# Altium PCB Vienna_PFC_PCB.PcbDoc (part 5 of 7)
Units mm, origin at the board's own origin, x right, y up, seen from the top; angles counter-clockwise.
Board outline 447.04 x 302.51 mm, 6 copper layers (Top Layer, Signal Layer 1, Signal Layer 2, Signal Layer 3, Signal Layer 4, Bottom Layer), stack 1.231 mm thick; 630 components, 255 nets, 1656 pads, 941 vias.
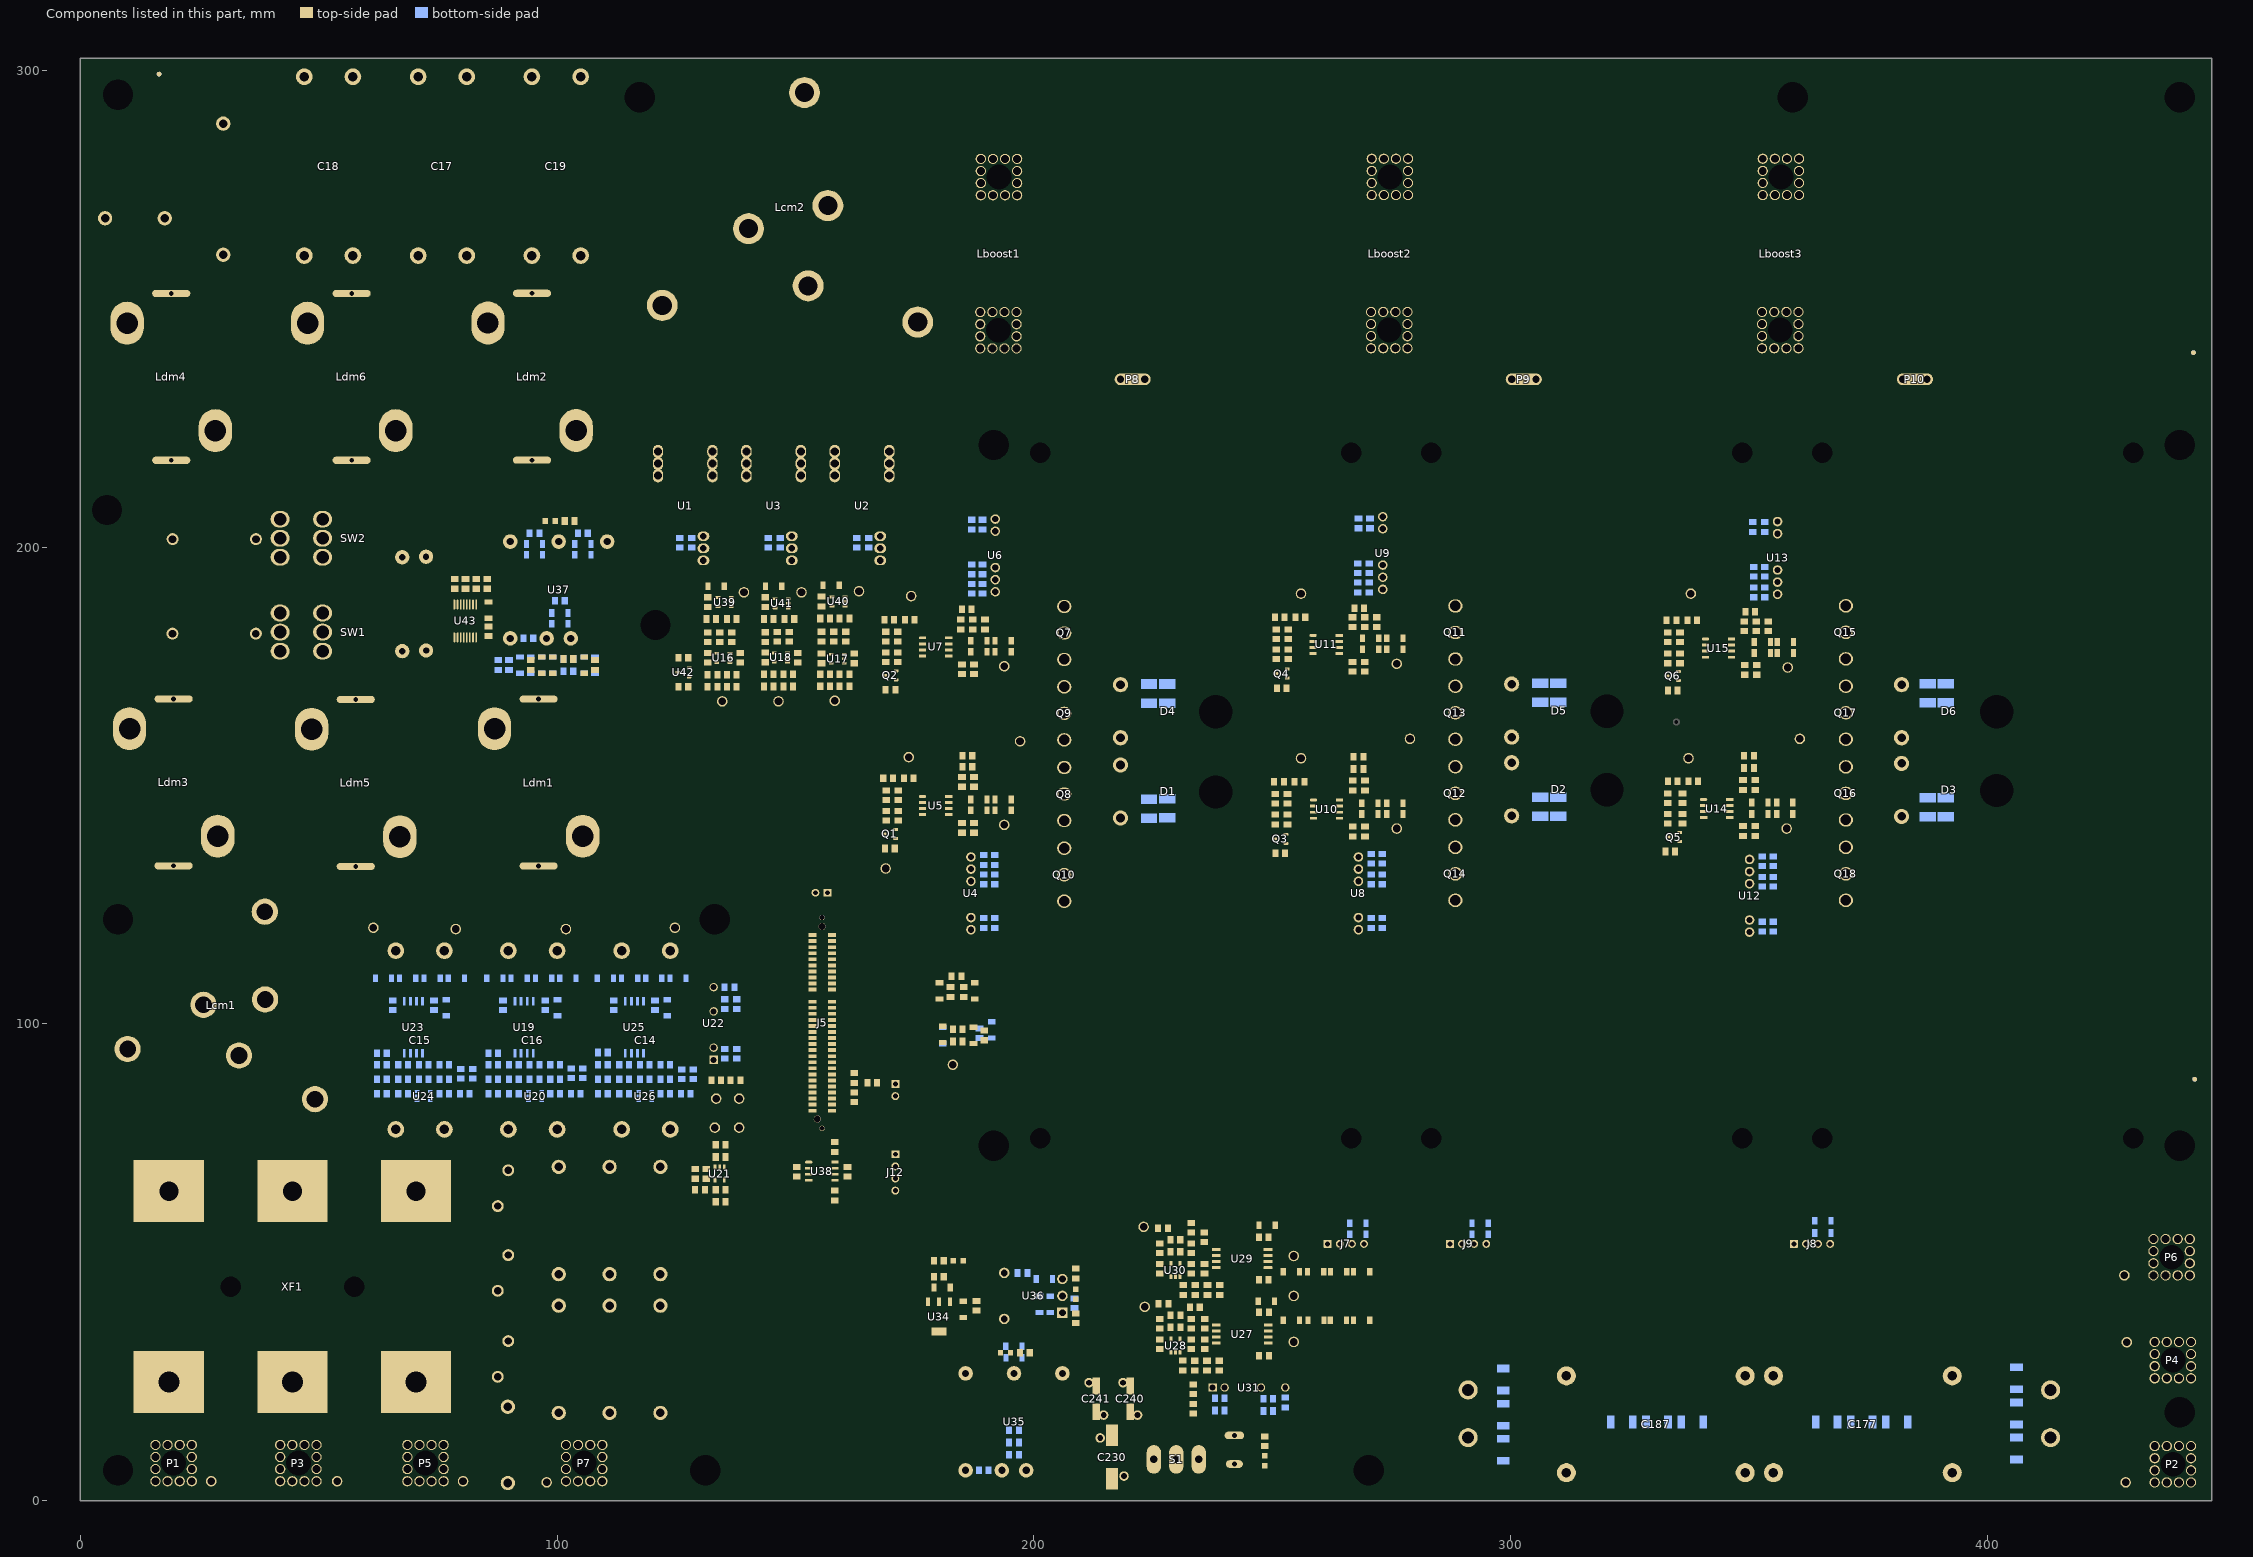
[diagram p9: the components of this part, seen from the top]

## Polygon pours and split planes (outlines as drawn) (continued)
NetQ17_1 on Top Layer "NONET_L-01_P-001" (solid, remove dead copper, pour order 825): 358.902,178.562 358.902,168.656 371.602,168.656 371.602,170.942 363.982,178.562
NetQ14_1 on Top Layer "NONET_L-01_P-001" (solid, remove dead copper, pour order 823): 276.86,144.78 276.86,134.874 289.56,134.874 289.56,137.16 281.94,144.78
NetQ13_1 on Top Layer "NONET_L-01_P-001" (solid, remove dead copper, pour order 821): 276.86,179.324 276.86,169.418 289.56,169.418 289.56,171.704 281.94,179.324
NetQ10_1 on Top Layer "NONET_L-01_P-001" (solid, remove dead copper, pour order 819): 194.818,145.542 194.818,135.636 207.01,135.89 207.01,137.922 199.898,145.542
NetQ16_1 on Top Layer "NONET_L-01_P-001" (solid, remove dead copper, pour order 817): 358.648,145.796 363.728,145.796 371.094,153.162 371.348,153.416 371.348,155.448 365.252,155.448 358.902,155.448 358.648,155.448
NetQ11_1 on Top Layer "NONET_L-01_P-001" (solid, remove dead copper, pour order 815): 276.86,180.086 281.94,180.086 289.306,187.452 289.56,187.706 289.56,189.738 283.464,189.738 277.114,189.738 276.86,189.738
NetQ15_1 on Top Layer "NONET_L-01_P-001" (solid, remove dead copper, pour order 813): 358.902,179.324 363.982,179.324 371.348,186.69 371.602,186.944 371.602,188.976 365.506,188.976 359.156,188.976 358.902,188.976
NetQ12_1 on Top Layer "NONET_L-01_P-001" (solid, remove dead copper, pour order 811): 276.86,145.542 281.94,145.542 289.306,152.908 289.56,153.162 289.56,155.194 283.464,155.194 277.114,155.194 276.86,155.194
NetQ8_1 on Top Layer "NONET_L-01_P-001" (solid, remove dead copper, pour order 807): 194.818,146.304 200.66,146.304 207.518,153.162 207.518,155.956 201.422,155.956 195.072,155.956 194.818,155.956
NetQ7_1 on Top Layer "NONET_L-01_P-001" (solid, remove dead copper, pour order 805): 194.818,179.578 199.898,179.578 207.264,186.944 207.518,187.198 207.518,189.23 201.422,189.23 195.072,189.23 194.818,189.23
NetQ9_1 on Top Layer "NONET_L-01_P-001" (solid, remove dead copper, pour order 803): 194.818,178.816 194.818,168.91 206.248,168.91 207.518,171.196 199.898,178.816
NetLcm1_1 on Top Layer "NONET_L-01_P-001" (solid, remove dead copper, pour order 42): 25 vertices, not listed, extent 2.542,32.512 90.932,108.966
NetLcm1_5 on Top Layer "NONET_L-01_P-001" (solid, remove dead copper, pour order 30): 91.186,54.864 91.186,50.038 85.344,44.196 59.436,44.196 49.784,44.196 35.814,58.166 28.194,65.786 28.194,81.026 28.194,97.536 36.322,97.536 36.322,77.724 42.418,71.628 52.578,71.628 52.578,61.468 59.182,54.864
NetLcm1_3 on Top Layer "NONET_L-01_P-001" (solid, remove dead copper, pour order 18): 24 vertices, not listed, extent 34.29,56.896 91.694,109.22
VBUSP on Top Layer "NONET_L-01_P-001" (solid, pour order 480): 424.205,99.06 420.37,99.06 205.232,99.06 205.232,66.294 424.205,66.294
NetD1_2 on Top Layer "NONET_L-01_P-001" (solid, remove dead copper, pour order 618): 26 vertices, not listed, extent 186.69,153.162 262.89,251.206
NetD2_2 on Top Layer "NONET_L-01_P-001" (solid, remove dead copper, pour order 630): 26 vertices, not listed, extent 268.986,153.67 344.424,251.206
V_BUS_M on Top Layer "NONET_L-01_P-001" (solid, remove dead copper, pour order 724): 18 vertices, not listed, extent 368.3,98.044 444.5,299.72
V_BUS_M on Top Layer "NONET_L-01_P-001" (solid, remove dead copper, pour order 728): 425.958,102.616 425.958,99.06 420.878,99.06 420.878,84.582 420.878,83.82 424.688,83.82 444.5,83.82 444.5,102.616
PE on Top Layer "NONET_L-01_P-001" (solid, remove dead copper, pour order 787): 123.698,2.286 123.698,64.77 98.552,64.77 98.552,2.286
DGND on Top Layer "NONET_L-01_P-001" (solid, pour order 860): 202.438,90.17 202.438,124.206 184.404,124.206 184.404,90.17
NetD3_2 on Top Layer "NONET_L-01_P-001" (solid, remove dead copper, pour order 642): 24 vertices, not listed, extent 351.028,153.67 422.91,251.206
VBUSP on Top Layer "NONET_L-01_P-001" (solid, remove dead copper, pour order 978): 393.7,102.87 381.254,102.87 381.254,142.748 382.778,144.272 393.7,144.272
VBUSN on Top Layer "NONET_L-01_P-001" (solid, remove dead copper, pour order 988): 396.722,102.888 421.36,102.888 421.36,175.292 408.674,175.292 380.652,175.292 380.652,171.535 380.72,171.468 385.546,171.468 393.928,171.468 395.198,170.198 396.722,168.674
GND on Signal Layer 1 "NONET_L-01_P-001" (solid, remove dead copper, pour order 1492): 55 vertices, not listed, extent 88.392,2.54 240.538,203.708
+3.3V_D on Signal Layer 1 "NONET_L-01_P-001" (solid, remove dead copper, pour order 496): 198.12,208.534 181.356,208.534 165.371,192.549 165.354,132.08 181.864,115.57 202.438,115.57 202.438,124.206 185.42,124.206 181.864,124.206 177.8,128.27 176.53,129.54 176.53,189.23 176.53,198.374 180.34,202.184 198.12,202.184
V_BUS_M on Signal Layer 1 "NONET_L-01_P-001" (solid, remove dead copper, pour order 1068): 34 vertices, not listed, extent 368.554,90.678 393.192,168.91
V_BUS_M on Signal Layer 1 "NONET_L-01_P-001" (solid, remove dead copper, pour order 708): 17 vertices, not listed, extent 205.232,2.032 444.5,99.06
GND on Signal Layer 1 "NONET_L-01_P-001" (solid, remove dead copper, pour order 837): 61.468,96.52 61.366,96.418 61.366,84.328 61.366,84.176 62.992,82.55 84.328,82.55 139.954,82.55 139.954,96.52
+3.3V_D on Signal Layer 1 "NONET_L-01_P-001" (solid, remove dead copper, pour order 532): 361.95,207.772 330.2,207.772 330.2,184.404 330.2,132.842 330.2,102.87 361.95,102.87 361.95,123.444 349.25,123.444 345.694,123.444 341.63,127.508 340.36,128.778 340.36,188.468 340.36,197.612 344.17,201.422 361.95,201.422
PE on Signal Layer 1 "NONET_L-01_P-001" (solid, remove dead copper, pour order 795): 123.698,2.159 123.698,64.77 98.298,64.77 98.298,2.159 110.871,2.159
NetC10_2 on Signal Layer 1 "NONET_L-01_P-001" (solid, remove dead copper, pour order 1252): 26 vertices, not listed, extent 36.068,120.904 110.236,145.796
DGND2 on Signal Layer 1 "NONET_L-01_P-001" (solid, remove dead copper, pour order 1490): 89.281,171.45 82.423,171.45 82.042,171.45 78.232,175.26 77.47,176.022 77.47,191.008 78.232,191.77 85.852,191.77 85.979,191.77 86.233,191.516 86.614,191.135 86.614,185.674 86.614,177.292 89.281,174.625
NetC20_1 on Signal Layer 1 "NONET_L-01_P-001" (solid, remove dead copper, pour order 1442): 12.7,276.86 10.16,274.32 10.16,264.16 12.7,261.62 13.97,260.35 30.48,260.35 33.02,262.89 33.782,263.652 33.782,273.812 30.734,276.86
NetC17_1 on Signal Layer 1 "NONET_L-01_P-001" (solid, remove dead copper, pour order 1430): 110.744,297.18 107.95,299.974 107.696,300.228 104.902,300.228 20.828,300.228 15.748,295.402 10.922,290.322 10.16,289.56 4.572,289.56 2.54,287.528 2.54,282.956 4.572,280.924 40.132,280.924 107.442,280.924 110.513,283.995
NetLboost3_1 on Signal Layer 1 "NONET_L-01_P-001" (solid, remove dead copper, pour order 1418): 38 vertices, not listed, extent 137.16,263.398 362.458,300.228
NetLboost2_1 on Signal Layer 1 "NONET_L-01_P-001" (solid, remove dead copper, pour order 1406): 20 vertices, not listed, extent 148.844,265.176 280.416,293.37
NetLboost1_1 on Signal Layer 1 "NONET_L-01_P-001" (solid, remove dead copper, pour order 1394): 150.114,256.286 151.384,255.016 151.384,252.476 172.466,252.476 189.23,269.24 195.58,269.24 198.374,272.034 198.374,282.448 197.612,283.21 178.054,283.21 152.4,257.556
NetLcm2_3 on Signal Layer 1 "NONET_L-01_P-001" (solid, remove dead copper, pour order 1382): 161.29,247.65 161.29,231.14 163.83,228.6 163.83,214.122 167.64,210.312 173.99,210.312 177.492,210.312 180.34,212.658 180.34,236.982 180.34,248.92 177.8,251.46 164.754,251.46
NetLcm2_5 on Signal Layer 1 "NONET_L-01_P-001" (solid, remove dead copper, pour order 1370): 32 vertices, not listed, extent 118.618,213.36 159.004,299.72
NetLcm2_1 on Signal Layer 1 "NONET_L-01_P-001" (solid, remove dead copper, pour order 1358): 123.444,254.254 117.856,248.666 120.65,245.872 128.27,238.252 128.27,228.092 128.27,215.392 129.794,213.868 130.302,213.36 133.35,213.36 134.112,213.36 135.128,214.376 135.636,214.884 135.636,235.966 135.636,242.062 131.318,246.38
NetC19_2 on Signal Layer 1 "NONET_L-01_P-001" (solid, remove dead copper, pour order 1348): 25 vertices, not listed, extent 77.47,212.852 125.222,264.16
NetC17_2 on Signal Layer 1 "NONET_L-01_P-001" (solid, remove dead copper, pour order 1334): 34 vertices, not listed, extent 44.196,213.614 143.51,278.13
NetC18_2 on Signal Layer 1 "NONET_L-01_P-001" (solid, remove dead copper, pour order 1322): 51 vertices, not listed, extent 5.08,205.232 162.814,278.13
NetLdm2_1 on Signal Layer 1 "NONET_L-01_P-001" (solid, remove dead copper, pour order 1308): 27 vertices, not listed, extent 46.99,175.26 107.442,231.648
NetLdm6_1 on Signal Layer 1 "NONET_L-01_P-001" (solid, remove dead copper, pour order 1298): 47.752,196.596 48.26,196.088 53.848,196.088 54.356,196.596 54.61,196.85 54.61,207.518 63.5,216.408 70.866,223.774 70.866,228.346 68.58,230.632 53.594,230.632 43.434,230.632 40.894,228.092 40.894,212.852 47.752,205.994
NetC16_2 on Signal Layer 1 "NONET_L-01_P-001" (solid, remove dead copper, pour order 1288): 27 vertices, not listed, extent 34.544,156.21 99.06,189.23
NetC15_2 on Signal Layer 1 "NONET_L-01_P-001" (solid, remove dead copper, pour order 1276): 31 vertices, not listed, extent 2.54,154.432 38.862,230.124
NetC15_2 on Signal Layer 1 "NONET_L-01_P-001" (solid, remove dead copper, pour order 1278): 31 vertices, not listed, extent 2.54,154.432 38.862,230.124
NetC14_2 on Signal Layer 1 "NONET_L-01_P-001" (solid, remove dead copper, pour order 1266): 30 vertices, not listed, extent 10.414,154.686 52.07,209.296
NetC8_2 on Signal Layer 1 "NONET_L-01_P-001" (solid, remove dead copper, pour order 1232): 32 vertices, not listed, extent 26.292,81.156 70.104,146.434
NetC9_2 on Signal Layer 1 "NONET_L-01_P-001" (solid, remove dead copper, pour order 1222): 17 vertices, not listed, extent 2.54,90.17 32.258,146.812
NetD3_2 on Signal Layer 1 "NONET_L-01_P-001" (solid, pour order 1170): 362.287,237.744 366.859,233.172 362.287,233.172
NetD2_2 on Signal Layer 1 "NONET_L-01_P-001" (solid, pour order 1156): 280.162,237.578 284.734,233.006 280.162,233.006
NetD1_2 on Signal Layer 1 "NONET_L-01_P-001" (solid, pour order 1144): 197.949,237.744 202.521,233.172 197.949,233.172
NetD3_2 on Signal Layer 1 "NONET_L-01_P-001" (solid, pour order 1130): 366.903,207.137 361.061,212.979 366.903,212.979
NetD2_2 on Signal Layer 1 "NONET_L-01_P-001" (solid, pour order 1122): 331.089,212.725 325.247,206.883 325.247,212.725
NetD2_2 on Signal Layer 1 "NONET_L-01_P-001" (solid, pour order 1112): 286.004,207.645 280.162,213.487 286.004,213.487
NetD1_2 on Signal Layer 1 "NONET_L-01_P-001" (solid, pour order 1102): 249.682,214.63 243.84,208.788 243.84,214.63
NetD1_2 on Signal Layer 1 "NONET_L-01_P-001" (solid, pour order 1094): 203.498,207.518 197.656,213.36 203.498,213.36
NetTVS1_1 on Signal Layer 1 "NONET_L-01_P-001" (solid, remove dead copper, pour order 1074): 24 vertices, not listed, extent 86.233,18.034 96.139,63.246
V_N_MEAS on Signal Layer 1 "NONET_L-01_P-001" (solid, remove dead copper, pour order 847): 135.636,101.6 61.468,101.6 61.214,101.854 61.214,110.49 135.636,110.49
+3.3V_D on Signal Layer 1 "NONET_L-01_P-001" (solid, remove dead copper, pour order 536): 361.696,105.664 184.15,105.664 184.15,117.348 301.752,117.348 361.586,117.348 361.696,117.238
+3.3V_D on Signal Layer 1 "NONET_L-01_P-001" (solid, remove dead copper, pour order 526): 280.162,208.788 248.412,208.788 248.412,185.42 248.412,133.858 248.412,102.87 280.162,102.87 280.162,124.46 267.462,124.46 263.906,124.46 259.842,128.524 258.572,129.794 258.572,189.484 258.572,198.628 262.382,202.438 280.162,202.438
NetLcm1_3 on Signal Layer 1 "NONET_L-01_P-001" (solid, remove dead copper, pour order 58): 24 vertices, not listed, extent 34.29,56.896 91.694,109.22
NetLcm1_1 on Signal Layer 1 "NONET_L-01_P-001" (solid, remove dead copper, pour order 46): 25 vertices, not listed, extent 2.545,31.496 91.186,108.966
NetLcm1_5 on Signal Layer 1 "NONET_L-01_P-001" (solid, remove dead copper, pour order 34): 90.932,54.865 90.932,49.7 85.429,44.197 59.521,44.197 49.869,44.197 35.899,58.167 28.279,65.787 28.279,81.027 28.279,97.537 36.407,97.537 36.407,77.725 42.503,71.629 52.663,71.629 52.663,61.469 59.267,54.865
+20V1 on Signal Layer 1 "NONET_L-01_P-001" (solid, remove dead copper, pour order 570): 182.88,198.12 182.88,162.56 198.12,162.56 198.12,198.12
-5V2 on Signal Layer 1 "NONET_L-01_P-001" (solid, remove dead copper, pour order 572): 182.88,127.762 198.12,127.762 198.12,157.48 182.88,157.48
+20V3 on Signal Layer 1 "NONET_L-01_P-001" (solid, remove dead copper, pour order 574): 264.922,198.628 264.922,162.56 280.162,162.56 280.162,198.628
-5V4 on Signal Layer 1 "NONET_L-01_P-001" (solid, remove dead copper, pour order 576): 264.922,127.508 280.162,127.508 280.162,157.48 264.922,157.48
+20V5 on Signal Layer 1 "NONET_L-01_P-001" (solid, remove dead copper, pour order 578): 346.71,197.866 346.71,162.56 361.95,162.56 361.95,197.866
-5V6 on Signal Layer 1 "NONET_L-01_P-001" (solid, remove dead copper, pour order 580): 346.71,126.746 361.95,126.746 361.95,157.48 346.71,157.48
NetD1_2 on Signal Layer 1 "NONET_L-01_P-001" (solid, remove dead copper, pour order 628): 26 vertices, not listed, extent 186.69,153.162 262.89,251.206
NetD2_2 on Signal Layer 1 "NONET_L-01_P-001" (solid, remove dead copper, pour order 640): 26 vertices, not listed, extent 268.986,153.67 344.424,251.206
NetD3_2 on Signal Layer 1 "NONET_L-01_P-001" (solid, remove dead copper, pour order 652): 24 vertices, not listed, extent 351.028,153.67 422.91,251.206
V_BUS_M on Signal Layer 1 "NONET_L-01_P-001" (solid, remove dead copper, pour order 720): 18 vertices, not listed, extent 368.3,98.044 444.5,299.72
V_BUS_M on Signal Layer 1 "NONET_L-01_P-001" (solid, remove dead copper, pour order 767): 246.38,17.526 246.38,58.674 255.778,58.674 255.778,47.752 255.778,17.78
VBUSP on Signal Layer 1 "NONET_L-01_P-001" (solid, remove dead copper, pour order 906): 230.124,120.65 217.678,120.65 217.678,142.748 219.202,144.272 230.124,144.272
VBUSN on Signal Layer 1 "NONET_L-01_P-001" (solid, remove dead copper, pour order 924): 232.918,120.65 245.11,120.65 245.11,175.514 244.87,175.274 216.849,175.274 216.849,171.517 216.916,171.45 221.742,171.45 230.124,171.45 231.394,170.18 232.918,168.656
VBUSP on Signal Layer 1 "NONET_L-01_P-001" (solid, remove dead copper, pour order 944): 312.166,120.65 299.72,120.65 299.72,142.748 301.244,144.272 312.166,144.272
VBUSN on Signal Layer 1 "NONET_L-01_P-001" (solid, remove dead copper, pour order 954): 314.96,120.65 326.898,120.65 326.898,139.192 326.898,175.26 326.949,175.311 326.912,175.274 298.891,175.274 298.891,171.517 298.958,171.45 303.784,171.45 312.166,171.45 313.436,170.18 314.96,168.656
VBUSP on Signal Layer 1 "NONET_L-01_P-001" (solid, remove dead copper, pour order 976): 393.7,102.87 381.254,102.87 381.254,142.748 382.778,144.272 393.7,144.272
VBUSN on Signal Layer 1 "NONET_L-01_P-001" (solid, remove dead copper, pour order 986): 396.722,102.888 421.36,102.888 421.36,175.292 408.674,175.292 380.652,175.292 380.652,171.535 380.72,171.468 385.546,171.468 393.928,171.468 395.198,170.198 396.722,168.674
GND1 on Signal Layer 1 "NONET_L-01_P-001" (solid, remove dead copper, pour order 1018): 34 vertices, not listed, extent 198.628,124.206 208.534,189.23
V_BUS_M on Signal Layer 1 "NONET_L-01_P-001" (solid, remove dead copper, pour order 1028): 34 vertices, not listed, extent 204.978,120.65 229.616,168.402
GND3 on Signal Layer 1 "NONET_L-01_P-001" (solid, remove dead copper, pour order 1036): 25 vertices, not listed, extent 280.67,124.238 289.572,189.738
V_BUS_M on Signal Layer 1 "NONET_L-01_P-001" (solid, remove dead copper, pour order 1046): 34 vertices, not listed, extent 287.02,120.65 311.658,168.91
GND5 on Signal Layer 1 "NONET_L-01_P-001" (solid, remove dead copper, pour order 1056): 25 vertices, not listed, extent 362.458,124.238 371.36,188.976
GND3 on Signal Layer 1 "NONET_L06_P1054" (solid, remove dead copper, pour order 1054): 25 vertices, not listed, extent 362.458,124.238 371.36,188.976
GND_IN on Signal Layer 1 "NONET_L-01_P-001" (solid, remove dead copper, pour order 1470): 189.23,14.986 183.896,9.652 181.102,6.858 181.102,4.064 181.102,3.81 182.88,2.032 190.246,2.032 254,2.032 255.27,3.302 255.27,14.478 254.762,14.986
12V_IN on Signal Layer 1 "NONET_L-01_P-001" (solid, remove dead copper, pour order 1472): 261.62,62.23 260.35,60.96 260.35,52.578 261.62,51.308 295.91,51.308 296.164,51.308 297.18,52.324 297.18,58.928 297.18,60.706 295.656,62.23
+3.3V on Signal Layer 2 "NONET_L-01_P-001" (solid, remove dead copper, pour order 1188): 54 vertices, not listed, extent 88.392,2.54 240.538,200.914
V_BUS_M on Signal Layer 2 "NONET_L-01_P-001" (solid, remove dead copper, pour order 1026): 35 vertices, not listed, extent 204.978,102.87 229.616,168.402
VBUSN on Signal Layer 2 "NONET_L-01_P-001" (solid, remove dead copper, pour order 922): 232.918,102.87 245.11,102.87 245.11,175.514 244.87,175.274 216.849,175.274 216.849,171.517 216.916,171.45 221.742,171.45 230.124,171.45 231.394,170.18 232.918,168.656
DGND on Signal Layer 2 "NONET_L-01_P-001" (solid, remove dead copper, pour order 534): 361.95,102.87 201.93,102.87 201.93,90.17 184.15,90.17 184.15,117.348 302.006,117.348 361.84,117.348 361.95,117.238
DGND on Signal Layer 2 "NONET_L-01_P-001" (solid, remove dead copper, pour order 310): 19 vertices, not listed, extent 166.37,115.57 202.438,208.534
VBUSN on Signal Layer 2 "NONET_L-01_P-001" (solid, remove dead copper, pour order 1494): 396.722,93.472 421.36,93.472 421.36,175.292 408.674,175.292 380.652,175.292 380.652,171.535 380.72,171.468 385.546,171.468 393.928,171.468 395.198,170.198 396.722,168.674
DGND on Signal Layer 2 "NONET_L-01_P-001" (solid, remove dead copper, pour order 312): 280.162,208.788 248.412,208.788 248.412,185.42 248.412,133.858 248.412,102.87 280.162,102.87 280.162,124.46 267.462,124.46 263.906,124.46 259.842,128.524 258.572,129.794 258.572,189.484 258.572,198.628 262.382,202.438 280.162,202.438
V_BUS_M on Signal Layer 2 "NONET_L-01_P-001" (solid, remove dead copper, pour order 1044): 34 vertices, not listed, extent 287.02,102.87 311.658,168.91
VBUSN on Signal Layer 2 "NONET_L-01_P-001" (solid, remove dead copper, pour order 952): 314.96,102.87 326.898,102.87 326.898,139.192 326.898,175.26 326.949,175.311 326.912,175.274 298.891,175.274 298.891,171.517 298.958,171.45 303.784,171.45 312.166,171.45 313.436,170.18 314.96,168.656
VBUSP on Signal Layer 2 "NONET_L-01_P-001" (solid, remove dead copper, pour order 940): 312.166,102.87 299.72,102.87 299.72,142.748 301.244,144.272 312.166,144.272
DGND on Signal Layer 2 "NONET_L-01_P-001" (solid, remove dead copper, pour order 314): 361.95,207.772 330.2,207.772 330.2,184.404 330.2,132.842 330.2,102.87 361.95,102.87 361.95,123.444 349.25,123.444 345.694,123.444 341.63,127.508 340.36,128.778 340.36,188.468 340.36,197.612 344.17,201.422 361.95,201.422
+3.3V on Signal Layer 2 "NONET_L-01_P-001" (solid, remove dead copper, pour order 755): 61.468,96.52 61.214,96.52 61.214,84.328 62.992,82.55 80.518,82.55 139.954,82.55 139.954,96.52 61.214,96.52
PE on Signal Layer 2 "NONET_L-01_P-001" (solid, remove dead copper, pour order 793): 123.698,2.286 123.698,64.77 98.298,64.77 98.298,2.286
DGND2 on Signal Layer 2 "NONET_L-01_P-001" (solid, remove dead copper, pour order 1488): 89.281,171.45 82.423,171.45 82.042,171.45 78.232,175.26 77.47,176.022 77.47,191.008 78.232,191.77 85.852,191.77 85.979,191.77 86.233,191.516 86.614,191.135 86.614,185.674 86.614,177.292 89.281,174.625
NetC20_1 on Signal Layer 2 "NONET_L-01_P-001" (solid, remove dead copper, pour order 1440): 12.7,276.86 10.16,274.32 10.16,264.16 12.7,261.62 13.97,260.35 30.48,260.35 33.02,262.89 33.782,263.652 33.782,273.812 30.734,276.86
NetC17_1 on Signal Layer 2 "NONET_L-01_P-001" (solid, remove dead copper, pour order 1428): 110.744,297.18 107.95,299.974 107.696,300.228 104.902,300.228 20.828,300.228 15.748,295.402 10.922,290.322 10.16,289.56 4.572,289.56 2.54,287.528 2.54,282.956 4.572,280.924 40.132,280.924 107.442,280.924 110.513,283.995
NetLboost3_1 on Signal Layer 2 "NONET_L-01_P-001" (solid, remove dead copper, pour order 1416): 38 vertices, not listed, extent 137.16,263.398 362.458,300.228
NetLboost2_1 on Signal Layer 2 "NONET_L-01_P-001" (solid, remove dead copper, pour order 1404): 20 vertices, not listed, extent 148.844,265.176 280.416,293.37
NetLboost1_1 on Signal Layer 2 "NONET_L-01_P-001" (solid, remove dead copper, pour order 1392): 150.114,256.286 151.384,255.016 151.384,252.476 172.466,252.476 189.23,269.24 195.58,269.24 198.374,272.034 198.374,282.448 197.612,283.21 178.054,283.21 152.4,257.556
NetLcm2_3 on Signal Layer 2 "NONET_L-01_P-001" (solid, remove dead copper, pour order 1380): 161.29,247.65 161.29,231.14 163.83,228.6 163.83,214.122 167.64,210.312 173.99,210.312 177.492,210.312 180.34,212.658 180.34,236.982 180.34,248.92 177.8,251.46 164.754,251.46
NetLcm2_5 on Signal Layer 2 "NONET_L-01_P-001" (solid, remove dead copper, pour order 1368): 32 vertices, not listed, extent 118.618,213.36 159.004,299.72
NetLcm2_1 on Signal Layer 2 "NONET_L-01_P-001" (solid, remove dead copper, pour order 1356): 123.444,254.254 117.856,248.666 120.65,245.872 128.27,238.252 128.27,228.092 128.27,215.392 129.794,213.868 130.302,213.36 133.35,213.36 134.112,213.36 135.128,214.376 135.636,214.884 135.636,235.966 135.636,242.062 131.318,246.38
NetC19_2 on Signal Layer 2 "NONET_L-01_P-001" (solid, remove dead copper, pour order 1346): 25 vertices, not listed, extent 77.47,212.852 125.222,264.16
NetC17_2 on Signal Layer 2 "NONET_L-01_P-001" (solid, remove dead copper, pour order 1332): 34 vertices, not listed, extent 44.196,213.614 143.51,278.13
NetC18_2 on Signal Layer 2 "NONET_L-01_P-001" (solid, remove dead copper, pour order 1320): 51 vertices, not listed, extent 5.08,205.232 162.814,278.13
NetLdm2_1 on Signal Layer 2 "NONET_L-01_P-001" (solid, remove dead copper, pour order 1306): 27 vertices, not listed, extent 46.99,175.26 107.442,231.648
NetLdm6_1 on Signal Layer 2 "NONET_L-01_P-001" (solid, remove dead copper, pour order 1296): 47.752,196.596 48.26,196.088 53.848,196.088 54.356,196.596 54.61,196.85 54.61,207.518 63.5,216.408 70.866,223.774 70.866,228.346 68.58,230.632 53.594,230.632 43.434,230.632 40.894,228.092 40.894,212.852 47.752,205.994
NetC16_2 on Signal Layer 2 "NONET_L-01_P-001" (solid, remove dead copper, pour order 1286): 27 vertices, not listed, extent 34.544,156.21 99.06,189.23
NetC15_2 on Signal Layer 2 "NONET_L-01_P-001" (solid, remove dead copper, pour order 1274): 31 vertices, not listed, extent 2.54,154.432 38.862,230.124
NetC14_2 on Signal Layer 2 "NONET_L-01_P-001" (solid, remove dead copper, pour order 1264): 30 vertices, not listed, extent 10.414,154.686 52.07,209.296
NetC8_2 on Signal Layer 2 "NONET_L-01_P-001" (solid, remove dead copper, pour order 1230): 32 vertices, not listed, extent 26.292,81.156 70.104,146.434
NetC9_2 on Signal Layer 2 "NONET_L-01_P-001" (solid, remove dead copper, pour order 1220): 17 vertices, not listed, extent 2.54,90.17 32.258,146.812
NetD3_2 on Signal Layer 2 "NONET_L-01_P-001" (solid, pour order 1168): 362.287,237.744 366.859,233.172 362.287,233.172
NetD2_2 on Signal Layer 2 "NONET_L-01_P-001" (solid, pour order 1158): 280.279,237.627 284.851,233.055 280.279,233.055
NetD1_2 on Signal Layer 2 "NONET_L-01_P-001" (solid, pour order 1142): 197.949,237.744 202.521,233.172 197.949,233.172
NetD3_2 on Signal Layer 2 "NONET_L-01_P-001" (solid, pour order 1128): 366.903,207.137 361.061,212.979 366.903,212.979
NetD2_2 on Signal Layer 2 "NONET_L-01_P-001" (solid, pour order 1120): 331.089,212.725 325.247,206.883 325.247,212.725
NetD2_2 on Signal Layer 2 "NONET_L-01_P-001" (solid, pour order 1110): 286.004,207.645 280.162,213.487 286.004,213.487
NetD1_2 on Signal Layer 2 "NONET_L-01_P-001" (solid, pour order 1100): 249.682,214.63 243.84,208.788 243.84,214.63
NetD1_2 on Signal Layer 2 "NONET_L-01_P-001" (solid, pour order 1092): 203.498,207.518 197.656,213.36 203.498,213.36
V_N_MEAS on Signal Layer 2 "NONET_L-01_P-001" (solid, remove dead copper, pour order 845): 135.636,101.6 61.468,101.6 61.214,101.854 61.214,110.49 135.636,110.49
NetLcm1_3 on Signal Layer 2 "NONET_L-01_P-001" (solid, remove dead copper, pour order 60): 24 vertices, not listed, extent 34.29,56.642 91.694,108.966
NetLcm1_1 on Signal Layer 2 "NONET_L-01_P-001" (solid, remove dead copper, pour order 48): 25 vertices, not listed, extent 2.584,31.496 91.186,108.966
NetLcm1_5 on Signal Layer 2 "NONET_L-01_P-001" (solid, remove dead copper, pour order 36): 90.932,54.864 90.932,49.784 85.344,44.196 59.436,44.196 49.784,44.196 35.814,58.166 28.194,65.786 28.194,81.026 28.194,97.536 36.322,97.536 36.322,77.724 42.418,71.628 52.578,71.628 52.578,61.468 59.182,54.864
GND1 on Signal Layer 2 "NONET_L-01_P-001" (solid, remove dead copper, pour order 302): 182.88,198.12 182.88,137.922 182.88,127.762 198.12,127.762 198.12,198.12
GND3 on Signal Layer 2 "NONET_L-01_P-001" (solid, remove dead copper, pour order 304): 264.922,198.628 264.922,138.43 264.922,127.508 280.162,127.508 280.162,198.628
GND5 on Signal Layer 2 "NONET_L-01_P-001" (solid, remove dead copper, pour order 306): 346.71,197.866 346.71,137.668 346.71,126.746 361.95,126.746 361.95,197.866
NetD1_2 on Signal Layer 2 "NONET_L-01_P-001" (solid, remove dead copper, pour order 626): 26 vertices, not listed, extent 186.69,153.162 262.89,251.206
NetD2_2 on Signal Layer 2 "NONET_L-01_P-001" (solid, remove dead copper, pour order 638): 26 vertices, not listed, extent 268.986,153.67 344.424,251.206
NetD3_2 on Signal Layer 2 "NONET_L-01_P-001" (solid, remove dead copper, pour order 650): 24 vertices, not listed, extent 351.028,153.67 422.91,251.206
VBUSN on Signal Layer 2 "NONET_L-01_P-001" (solid, remove dead copper, pour order 716): 215.138,99.06 205.232,99.06 205.232,66.294 300.99,66.294 300.99,46.99 274.32,46.99 274.32,2.032 444.5,2.032 424.18,2.032 424.18,45.72 444.5,45.72 444.5,66.548 444.246,66.802 421.64,66.802 421.64,99.06
V_BUS_M on Signal Layer 2 "NONET_L-01_P-001" (solid, remove dead copper, pour order 722): 18 vertices, not listed, extent 368.3,98.044 444.5,299.72
5V_N on Signal Layer 2 "NONET_L-01_P-001" (solid, remove dead copper, pour order 752): 134.112,106.426 134.112,103.886 119.634,103.886 64.516,103.886 64.516,105.918 76.708,105.918 131.572,105.918 131.572,106.426
V_BUS_M on Signal Layer 2 "NONET_L-01_P-001" (solid, remove dead copper, pour order 765): 246.38,17.526 246.38,58.674 255.778,58.674 255.778,47.752 255.778,17.78
VBUSP on Signal Layer 2 "NONET_L-01_P-001" (solid, remove dead copper, pour order 904): 230.124,119.888 217.678,119.888 217.678,142.748 219.202,144.272 230.124,144.272
VBUSP on Signal Layer 2 "NONET_L-01_P-001" (solid, remove dead copper, pour order 974): 393.7,102.87 381.254,102.87 381.254,142.748 382.778,144.272 393.7,144.272
GND1 on Signal Layer 2 "NONET_L-01_P-001" (solid, remove dead copper, pour order 1016): 34 vertices, not listed, extent 198.628,124.206 208.534,189.23
GND3 on Signal Layer 2 "NONET_L-01_P-001" (solid, remove dead copper, pour order 1034): 25 vertices, not listed, extent 280.67,124.238 289.572,189.738
GND5 on Signal Layer 2 "NONET_L-01_P-001" (solid, remove dead copper, pour order 1052): 25 vertices, not listed, extent 362.458,124.238 371.36,188.976
V_BUS_M on Signal Layer 2 "NONET_L-01_P-001" (solid, remove dead copper, pour order 1064): 34 vertices, not listed, extent 368.554,102.87 393.192,168.91
GND_IN on Signal Layer 2 "NONET_L-01_P-001" (solid, remove dead copper, pour order 1468): 189.23,14.986 183.896,9.652 181.102,6.858 181.102,4.064 181.102,3.81 182.88,2.032 190.246,2.032 254,2.032 255.27,3.302 255.27,14.478 254.762,14.986
12V_IN on Signal Layer 2 "NONET_L-01_P-001" (solid, remove dead copper, pour order 1478): 261.62,62.23 260.35,60.96 260.35,52.578 261.62,51.308 295.91,51.308 296.164,51.308 297.18,52.324 297.18,58.928 297.18,60.706 295.656,62.23
GND on Signal Layer 3 "NONET_L-01_P-001" (solid, remove dead copper, pour order 1182): 54 vertices, not listed, extent 88.392,2.54 240.538,200.914
DGND on Signal Layer 3 "NONET_L-01_P-001" (solid, remove dead copper, pour order 524): 198.12,208.534 181.356,208.534 165.354,192.532 165.354,132.08 181.864,115.57 202.438,115.57 202.438,124.206 185.42,124.206 181.864,124.206 177.8,128.27 176.53,129.54 176.53,189.23 176.53,198.374 180.34,202.184 198.12,202.184
VBUSN on Signal Layer 3 "NONET_L-01_P-001" (solid, remove dead copper, pour order 492): 300.99,66.802 300.99,46.99 276.86,46.99 274.32,46.99 274.32,2.032 424.18,2.032 424.18,54.61 424.18,66.802
VBUSN on Signal Layer 3 "NONET_L-01_P-001" (solid, remove dead copper, pour order 890): 314.96,91.44 326.898,91.44 326.898,139.192 326.898,175.26 326.949,175.311 326.912,175.274 298.891,175.274 298.891,171.517 298.958,171.45 303.784,171.45 312.166,171.45 313.436,170.18 314.96,168.656
VBUSN on Signal Layer 3 "NONET_L-01_P-001" (solid, remove dead copper, pour order 880): 232.918,92.964 245.11,92.964 245.11,175.514 244.87,175.274 216.849,175.274 216.849,171.517 216.916,171.45 221.742,171.45 230.124,171.45 231.394,170.18 232.918,168.656
DGND on Signal Layer 3 "NONET_L-01_P-001" (solid, remove dead copper, pour order 530): 361.95,207.772 330.2,207.772 330.2,184.404 330.2,132.842 330.2,102.87 361.95,102.87 361.95,123.444 349.25,123.444 345.694,123.444 341.63,127.508 340.36,128.778 340.36,188.468 340.36,197.612 344.17,201.422 361.95,201.422
VBUSN on Signal Layer 3 "NONET_L-01_P-001" (solid, remove dead copper, pour order 896): 396.722,93.472 421.36,93.472 421.36,175.292 408.674,175.292 380.652,175.292 380.652,171.535 380.72,171.468 385.546,171.468 393.928,171.468 395.198,170.198 396.722,168.674
VBUSP on Signal Layer 3 "NONET_L-01_P-001" (solid, remove dead copper, pour order 946): 312.166,102.87 299.72,102.87 299.72,142.748 301.244,144.272 312.166,144.272
V_BUS_M on Signal Layer 3 "NONET_L-01_P-001" (solid, remove dead copper, pour order 1040): 34 vertices, not listed, extent 287.02,102.87 311.658,168.91
VBUSP on Signal Layer 3 "NONET_L-01_P-001" (solid, remove dead copper, pour order 902): 230.124,102.87 217.678,102.87 217.678,142.748 219.202,144.272 230.124,144.272
V_BUS_M on Signal Layer 3 "NONET_L-01_P-001" (solid, remove dead copper, pour order 1022): 35 vertices, not listed, extent 204.978,102.87 229.616,168.402
VBUSN on Signal Layer 3 "NONET_L-01_P-001" (solid, pour order 482): 421.64,99.06 420.37,99.06 205.232,99.06 205.232,66.294 421.64,66.294
V_BUS_M on Signal Layer 3 "NONET_L-01_P-001" (solid, remove dead copper, pour order 1060): 34 vertices, not listed, extent 368.554,102.87 393.192,168.91
GND on Signal Layer 3 "NONET_L-01_P-001" (solid, remove dead copper, pour order 753): 61.468,96.52 61.468,85.344 64.262,82.55 83.82,82.55 139.446,82.55 139.446,96.52
PE on Signal Layer 3 "NONET_L-01_P-001" (solid, remove dead copper, pour order 791): 123.698,2.286 123.698,64.77 98.298,64.77 98.298,2.286
NetLcm1_3 on Signal Layer 3 "NONET_L-01_P-001" (solid, remove dead copper, pour order 62): 24 vertices, not listed, extent 34.29,56.896 91.694,109.22
NetC10_2 on Signal Layer 3 "NONET_L-01_P-001" (solid, remove dead copper, pour order 1250): 26 vertices, not listed, extent 36.068,120.904 110.236,145.796
DGND2 on Signal Layer 3 "NONET_L-01_P-001" (solid, remove dead copper, pour order 1486): 89.281,171.45 82.423,171.45 82.042,171.45 78.232,175.26 77.47,176.022 77.47,191.008 78.232,191.77 85.852,191.77 85.979,191.77 86.233,191.516 86.614,191.135 86.614,185.674 86.614,177.292 89.281,174.625
NetC20_1 on Signal Layer 3 "NONET_L-01_P-001" (solid, remove dead copper, pour order 1438): 12.7,276.86 10.16,274.32 10.16,264.16 12.7,261.62 13.97,260.35 30.48,260.35 33.02,262.89 33.782,263.652 33.782,273.812 30.734,276.86
NetC17_1 on Signal Layer 3 "NONET_L-01_P-001" (solid, remove dead copper, pour order 1426): 110.744,297.18 107.95,299.974 107.696,300.228 104.902,300.228 20.828,300.228 15.748,295.402 10.922,290.322 10.16,289.56 4.572,289.56 2.54,287.528 2.54,282.956 4.572,280.924 40.132,280.924 107.442,280.924 110.513,283.995
NetLboost3_1 on Signal Layer 3 "NONET_L-01_P-001" (solid, remove dead copper, pour order 1414): 38 vertices, not listed, extent 137.16,263.398 362.458,300.228
NetLboost2_1 on Signal Layer 3 "NONET_L-01_P-001" (solid, remove dead copper, pour order 1402): 20 vertices, not listed, extent 148.844,265.176 280.416,293.37
NetLboost1_1 on Signal Layer 3 "NONET_L-01_P-001" (solid, remove dead copper, pour order 1390): 150.114,256.286 151.384,255.016 151.384,252.476 172.466,252.476 189.23,269.24 195.58,269.24 198.374,272.034 198.374,282.448 197.612,283.21 178.054,283.21 152.4,257.556
NetLcm2_3 on Signal Layer 3 "NONET_L-01_P-001" (solid, remove dead copper, pour order 1378): 161.29,247.65 161.29,231.14 163.83,228.6 163.83,214.122 167.64,210.312 180.34,220.771 180.34,236.982 180.34,248.92 177.8,251.46 164.754,251.46
NetLcm2_5 on Signal Layer 3 "NONET_L-01_P-001" (solid, remove dead copper, pour order 1366): 32 vertices, not listed, extent 118.618,213.36 159.004,299.72
NetLcm2_1 on Signal Layer 3 "NONET_L-01_P-001" (solid, remove dead copper, pour order 1354): 123.444,254.254 117.856,248.666 120.65,245.872 128.27,238.252 128.27,228.092 128.27,215.392 129.794,213.868 130.302,213.36 133.35,213.36 134.112,213.36 135.128,214.376 135.636,214.884 135.636,235.966 135.636,242.062 131.318,246.38
NetC19_2 on Signal Layer 3 "NONET_L-01_P-001" (solid, remove dead copper, pour order 1344): 25 vertices, not listed, extent 77.47,212.852 125.222,264.16
NetC17_2 on Signal Layer 3 "NONET_L-01_P-001" (solid, remove dead copper, pour order 1328): 34 vertices, not listed, extent 44.196,213.614 143.51,278.13
NetC18_2 on Signal Layer 3 "NONET_L-01_P-001" (solid, remove dead copper, pour order 1318): 51 vertices, not listed, extent 5.08,205.232 162.814,278.13
NetLdm2_1 on Signal Layer 3 "NONET_L-01_P-001" (solid, remove dead copper, pour order 1304): 27 vertices, not listed, extent 46.99,175.26 107.442,231.648
NetLdm6_1 on Signal Layer 3 "NONET_L-01_P-001" (solid, remove dead copper, pour order 1294): 47.752,196.596 48.26,196.088 53.848,196.088 54.356,196.596 54.61,196.85 54.61,207.518 63.5,216.408 70.866,223.774 70.866,227.203 67.437,230.632 53.594,230.632 43.434,230.632 40.894,228.092 40.894,212.852 47.752,205.994
NetC16_2 on Signal Layer 3 "NONET_L-01_P-001" (solid, remove dead copper, pour order 1284): 27 vertices, not listed, extent 34.544,156.21 99.06,189.23
NetC14_2 on Signal Layer 3 "NONET_L-01_P-001" (solid, remove dead copper, pour order 1262): 30 vertices, not listed, extent 10.414,154.686 52.07,209.296
NetC8_2 on Signal Layer 3 "NONET_L-01_P-001" (solid, remove dead copper, pour order 1228): 32 vertices, not listed, extent 26.292,81.156 70.104,146.434
NetC9_2 on Signal Layer 3 "NONET_L-01_P-001" (solid, remove dead copper, pour order 1218): 17 vertices, not listed, extent 2.54,90.17 32.258,146.812
NetD3_2 on Signal Layer 3 "NONET_L-01_P-001" (solid, pour order 1132): 366.903,207.137 361.061,212.979 366.903,212.979
NetD2_2 on Signal Layer 3 "NONET_L-01_P-001" (solid, pour order 1118): 331.089,212.725 325.247,206.883 325.247,212.725
NetD2_2 on Signal Layer 3 "NONET_L-01_P-001" (solid, pour order 1108): 286.004,207.645 280.162,213.487 286.004,213.487
NetD1_2 on Signal Layer 3 "NONET_L-01_P-001" (solid, pour order 1098): 249.682,214.63 243.84,208.788 243.84,214.63
NetD1_2 on Signal Layer 3 "NONET_L-01_P-001" (solid, pour order 1090): 203.498,207.518 197.656,213.36 203.498,213.36
DGND on Signal Layer 3 "NONET_L-01_P-001" (solid, remove dead copper, pour order 528): 280.162,208.788 248.412,208.788 248.412,185.42 248.412,133.858 248.412,102.87 280.162,102.87 280.162,124.46 267.462,124.46 263.906,124.46 259.842,128.524 258.572,129.794 258.572,189.484 258.572,198.628 262.382,202.438 280.162,202.438
GND5 on Signal Layer 3 "NONET_L-01_P-001" (solid, remove dead copper, pour order 516): 346.71,197.866 346.71,137.668 346.71,126.746 361.95,126.746 361.95,197.866
GND3 on Signal Layer 3 "NONET_L-01_P-001" (solid, remove dead copper, pour order 512): 264.922,198.628 264.922,138.43 264.922,127.508 280.162,127.508 280.162,198.628
GND1 on Signal Layer 3 "NONET_L-01_P-001" (solid, remove dead copper, pour order 504): 182.88,198.12 182.88,137.922 182.88,127.762 198.12,127.762 198.12,198.12
NetLcm1_1 on Signal Layer 3 "NONET_L-01_P-001" (solid, remove dead copper, pour order 50): 20 vertices, not listed, extent 5.08,43.434 48.006,108.966
NetLcm1_5 on Signal Layer 3 "NONET_L-01_P-001" (solid, remove dead copper, pour order 38): 90.932,54.864 90.932,49.784 85.344,44.196 49.784,44.196 35.814,58.166 28.194,65.786 28.194,81.026 28.194,97.536 36.322,97.536 36.322,77.724 42.418,71.628 52.578,71.628 52.578,61.468 59.182,54.864
NetC9_2 on Signal Layer 3 "NONET_L-01_P-001" (solid, remove dead copper, pour order 542): 18 vertices, not listed, extent 2.54,33.528 112.522,97.282
NetD1_2 on Signal Layer 3 "NETD1_2_L04_P624" (solid, remove dead copper, pour order 624): 26 vertices, not listed, extent 186.69,153.162 262.89,251.206
NetD2_2 on Signal Layer 3 "NONET_L-01_P-001" (solid, remove dead copper, pour order 636): 26 vertices, not listed, extent 268.986,153.67 344.424,251.206
NetD3_2 on Signal Layer 3 "NONET_L-01_P-001" (solid, remove dead copper, pour order 648): 24 vertices, not listed, extent 351.028,153.67 422.91,251.206
V_BUS_M on Signal Layer 3 "NONET_L-01_P-001" (solid, remove dead copper, pour order 712): 18 vertices, not listed, extent 368.3,98.044 444.5,299.72
V_N_MEAS on Signal Layer 3 "NONET_L-01_P-001" (solid, remove dead copper, pour order 757): 135.636,101.6 61.468,101.6 61.214,101.854 61.214,110.49 135.636,110.49
V_BUS_M on Signal Layer 3 "NONET_L-01_P-001" (solid, remove dead copper, pour order 759): 246.38,17.526 246.38,58.674 255.778,58.674 255.778,47.752 255.778,17.78
VBUSP on Signal Layer 3 "NONET_L-01_P-001" (solid, remove dead copper, pour order 972): 393.7,102.87 381.254,102.87 381.254,142.748 382.778,144.272 393.7,144.272
GND1 on Signal Layer 3 "NONET_L-01_P-001" (solid, remove dead copper, pour order 1014): 34 vertices, not listed, extent 198.628,124.206 208.534,189.23
GND3 on Signal Layer 3 "NONET_L-01_P-001" (solid, remove dead copper, pour order 1032): 25 vertices, not listed, extent 280.67,124.238 289.572,189.738
GND5 on Signal Layer 3 "NONET_L-01_P-001" (solid, remove dead copper, pour order 1050): 25 vertices, not listed, extent 362.458,124.238 371.36,188.976
NetC15_2 on Signal Layer 3 "NONET_L-01_P-001" (solid, remove dead copper, pour order 1444): 31 vertices, not listed, extent 2.54,154.432 38.862,230.124
GND_IN on Signal Layer 3 "NONET_L-01_P-001" (solid, remove dead copper, pour order 1466): 189.23,14.986 183.896,9.652 181.102,6.858 181.102,4.064 181.102,3.81 182.88,2.032 190.246,2.032 254,2.032 255.27,3.302 255.27,14.478 254.762,14.986
12V_IN on Signal Layer 3 "NONET_L-01_P-001" (solid, remove dead copper, pour order 1476): 261.62,62.23 260.35,60.96 260.35,52.578 261.62,51.308 295.91,51.308 296.164,51.308 297.18,52.324 297.18,58.928 297.18,60.706 295.656,62.23
+5V on Signal Layer 4 "NONET_L-01_P-001" (solid, remove dead copper, pour order 1186): 55 vertices, not listed, extent 88.392,2.54 240.538,200.914
DGND on Signal Layer 4 "NONET_L-01_P-001" (solid, remove dead copper, pour order 546): 198.12,208.534 181.356,208.534 165.354,192.532 165.354,132.08 181.864,115.57 202.438,115.57 202.438,124.206 185.42,124.206 181.864,124.206 177.8,128.27 176.53,129.54 176.53,189.23 176.53,198.374 180.34,202.184 198.12,202.184
V_BUS_M on Signal Layer 4 "NONET_L-01_P-001" (solid, remove dead copper, pour order 710): 17 vertices, not listed, extent 205.232,2.032 444.5,99.06
V_BUS_M on Signal Layer 4 "NONET_L-01_P-001" (solid, remove dead copper, pour order 1062): 34 vertices, not listed, extent 368.554,94.488 393.192,168.91
V_BUS_M on Signal Layer 4 "NONET_L-01_P-001" (solid, remove dead copper, pour order 1048): 34 vertices, not listed, extent 287.02,93.98 311.658,168.91
VBUSP on Signal Layer 4 "NONET_L-01_P-001" (solid, remove dead copper, pour order 894): 393.7,102.87 381.254,102.87 381.254,142.748 382.778,144.272 393.7,144.272
VBUSP on Signal Layer 4 "NONET_L-01_P-001" (solid, remove dead copper, pour order 888): 312.166,102.87 299.72,102.87 299.72,142.748 301.244,144.272 312.166,144.272
VBUSP on Signal Layer 4 "NONET_L-01_P-001" (solid, remove dead copper, pour order 878): 230.124,102.87 217.678,102.87 217.678,142.748 219.202,144.272 230.124,144.272
V_BUS_M on Signal Layer 4 "NONET_L-01_P-001" (solid, remove dead copper, pour order 1030): 35 vertices, not listed, extent 205.232,92.456 229.87,168.402
GND on Signal Layer 4 "NONET_L-01_P-001" (solid, remove dead copper, pour order 835): 61.468,96.52 61.366,96.418 61.366,84.328 61.366,84.176 62.992,82.55 84.328,82.55 127.762,82.55 127.762,96.52
DGND on Signal Layer 4 "NONET_L-01_P-001" (solid, remove dead copper, pour order 564): 361.95,207.772 330.2,207.772 330.2,184.404 330.2,132.842 330.2,102.87 361.95,102.87 361.95,123.444 349.25,123.444 345.694,123.444 341.63,127.508 340.36,128.778 340.36,188.468 340.36,197.612 344.17,201.422 361.95,201.422
PE on Signal Layer 4 "NONET_L-01_P-001" (solid, remove dead copper, pour order 789): 123.698,2.286 123.698,64.77 98.298,64.77 98.298,2.286
NetC10_2 on Signal Layer 4 "NONET_L-01_P-001" (solid, remove dead copper, pour order 1248): 26 vertices, not listed, extent 36.068,120.904 110.236,145.796
DGND2 on Signal Layer 4 "NONET_L-01_P-001" (solid, remove dead copper, pour order 1484): 89.281,171.45 82.423,171.45 82.042,171.45 78.232,175.26 77.47,176.022 77.47,191.008 78.232,191.77 85.852,191.77 85.979,191.77 86.233,191.516 86.614,191.135 86.614,185.674 86.614,177.292 89.281,174.625
NetC20_1 on Signal Layer 4 "NONET_L-01_P-001" (solid, remove dead copper, pour order 1436): 12.7,276.86 10.16,274.32 10.16,264.16 12.7,261.62 13.97,260.35 30.48,260.35 33.02,262.89 33.782,263.652 33.782,273.812 30.734,276.86
NetC17_1 on Signal Layer 4 "NONET_L-01_P-001" (solid, remove dead copper, pour order 1424): 110.744,297.18 107.95,299.974 107.696,300.228 104.902,300.228 20.828,300.228 15.748,295.402 10.922,290.322 10.16,289.56 4.572,289.56 2.54,287.528 2.54,282.956 4.572,280.924 40.132,280.924 107.442,280.924 110.513,283.995
NetLboost3_1 on Signal Layer 4 "NONET_L-01_P-001" (solid, remove dead copper, pour order 1412): 38 vertices, not listed, extent 137.16,263.398 362.458,300.228
NetLboost2_1 on Signal Layer 4 "NONET_L-01_P-001" (solid, remove dead copper, pour order 1400): 20 vertices, not listed, extent 148.844,265.176 280.416,293.37
NetLboost1_1 on Signal Layer 4 "NONET_L-01_P-001" (solid, remove dead copper, pour order 1388): 150.114,256.286 151.384,255.016 151.384,252.476 172.466,252.476 189.23,269.24 195.58,269.24 198.374,272.034 198.374,282.448 197.612,283.21 178.054,283.21 152.4,257.556
NetLcm2_3 on Signal Layer 4 "NONET_L-01_P-001" (solid, remove dead copper, pour order 1376): 161.29,247.65 161.29,231.14 163.83,228.6 163.83,214.122 167.64,210.312 173.99,210.312 177.492,210.312 180.34,212.658 180.34,236.982 180.34,248.92 177.8,251.46 164.754,251.46
NetLcm2_5 on Signal Layer 4 "NONET_L-01_P-001" (solid, remove dead copper, pour order 1364): 32 vertices, not listed, extent 118.618,213.36 159.004,299.72
NetLcm2_1 on Signal Layer 4 "NONET_L-01_P-001" (solid, remove dead copper, pour order 1352): 123.444,254.254 117.856,248.666 120.65,245.872 128.27,238.252 128.27,228.092 128.27,215.392 129.794,213.868 130.302,213.36 133.35,213.36 134.112,213.36 135.128,214.376 135.636,214.884 135.636,235.966 135.636,242.062 131.318,246.38
NetC19_2 on Signal Layer 4 "NONET_L-01_P-001" (solid, remove dead copper, pour order 1342): 25 vertices, not listed, extent 77.47,212.852 125.222,264.16
NetC17_2 on Signal Layer 4 "NONET_L-01_P-001" (solid, remove dead copper, pour order 1326): 34 vertices, not listed, extent 44.196,213.614 143.51,278.13
NetC18_2 on Signal Layer 4 "NONET_L-01_P-001" (solid, remove dead copper, pour order 1316): 51 vertices, not listed, extent 5.08,205.232 162.814,278.13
